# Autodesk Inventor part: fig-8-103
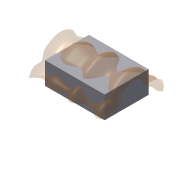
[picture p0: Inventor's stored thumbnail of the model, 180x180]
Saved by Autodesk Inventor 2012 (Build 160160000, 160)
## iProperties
Shininess: 64.0
Length Units: 11269
Angle Units: 11279
Time Units: 11290
Mass Units: 11283
Length Display Precision: 3
Angle Display Precision: 2
Compacted: True
Part Number: fig-8-103
Document SubType Name: Modeling
Created: 2002-12
Designer: deepak
Density: 1 g/cm^3
Material: Default
Density: 0.0
Volumn: 0.0
Area: 0.0
PropertySet Name: Model Information
Control State: 0
Master: False
Checked Out: False
Author: deepak
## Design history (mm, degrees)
sketch "Sketch1"
  geometry: L1 (-34.987, 25.636)-(31.934, 25.636); L2 (31.934, 25.636)-(31.934, -23.728); L3 (31.934, -23.728)-(-34.987, -23.728); L4 (-34.987, -23.728)-(-34.987, 25.636)
  constraints: 8 end point, 2 parallel, 1 horizontal, 1 perpendicular
extrude "Extrusion1" new body sketch "Sketch1" distance "d0" = 25; taper "d1" = 0 deg
sketch "Sketch2"
  geometry: 14 further points
  constraints: 14 other
workplane "Work Plane1"
sketch "Sketch3"
  geometry: 8 further points
  constraints: 8 other
feature "SweepSrf1" sketch "Sketch3" dims "d2" = 0
body "Solid1"
body "Srf1"
